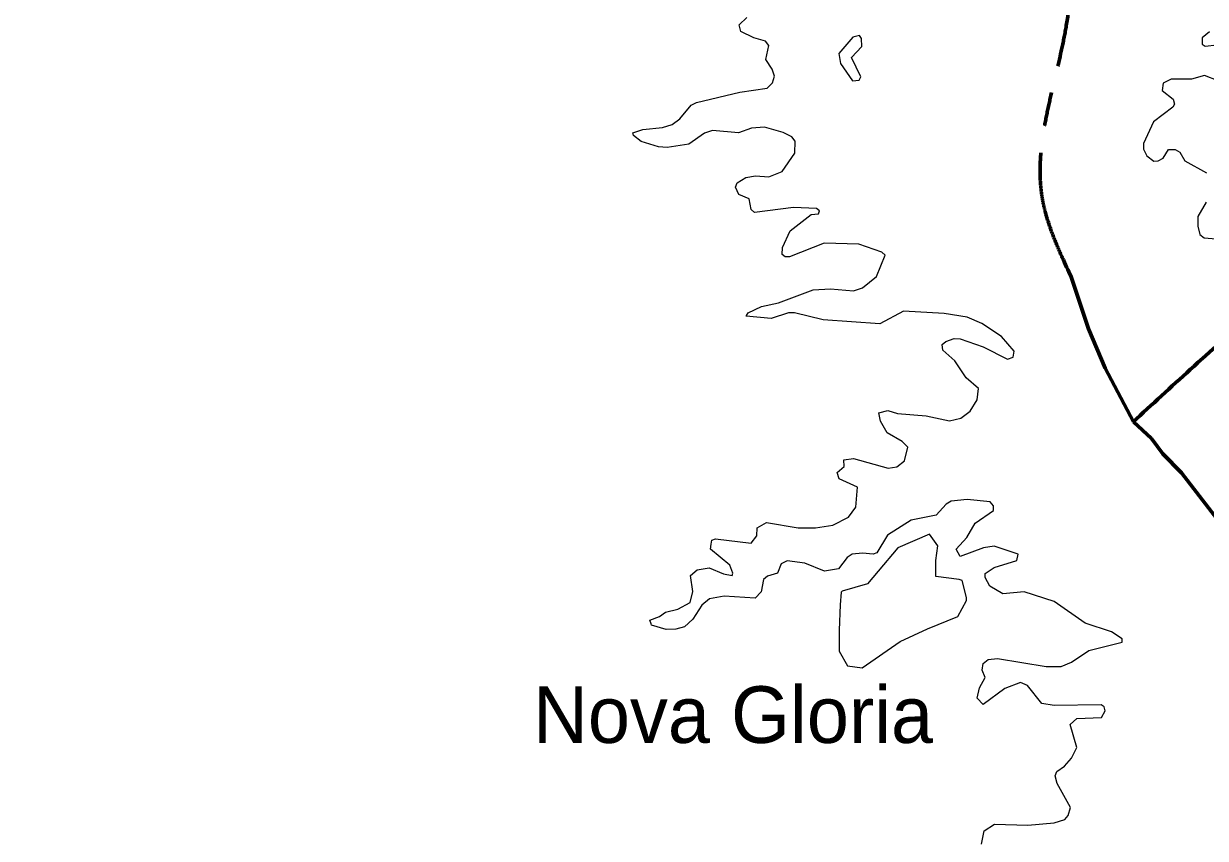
# Model space of a CAD drawing. Extents: x -1643653 to 4543381, y 1624270 to 13878484.
# Drawn here: x 573929 to 584359, y 8965010 to 8972200 of the extents above; entities that cross this region are included whole.
import ezdxf
from ezdxf.enums import TextEntityAlignment as Align

# ---------------------------------------------------------------- set-up
doc = ezdxf.new("R2010")
doc.units = 0
doc.header["$LTSCALE"] = 200
doc.linetypes.add('LONG_DASH_SHORT_DASH', pattern=[9.9, 6, -1.2, 1.5, -1.2])
for name, color, linetype, lineweight in [('21', 7, 'Continuous', 25), ('25', 7, 'Continuous', 13), ('60', 7, 'Continuous', 13), ('7', 7, 'LONG_DASH_SHORT_DASH', 60)]:
    doc.layers.add(name, color=color, linetype=linetype, lineweight=lineweight)
doc.layers.add('41', color=7, linetype='Continuous')

msp = doc.modelspace()

# ---------------------------------------------------------------- linework, layer by layer
at = {"layer": '21'}
msp.add_lwpolyline([(581144.7, 8967182.6), (581135.4, 8967071.1), (581126.2, 8966848.2), (581126.2, 8966662.4), (581200.4, 8966532.3), (581330.4, 8966513.8), (581664.7, 8966746), (581906.1, 8966857.5), (582175.4, 8966968.9), (582249.7, 8967108.2), (582249.7, 8967136.1), (582212.6, 8967284.7), (582184.7, 8967294), (581980.4, 8967321.9), (581980.4, 8967461.2), (581999, 8967591.2), (581924.7, 8967693.4), (581646.1, 8967572.7), (581469.7, 8967368.3), (581376.9, 8967256.9), (581154, 8967191.8)], close=True, dxfattribs=at)
at = {"layer": '25'}
msp.add_line((579471.8, 8966890.6), (579467.6, 8966902.2), dxfattribs=at)
msp.add_line((579471.8, 8966890.6), (579467.6, 8966902.2), dxfattribs=at)
for points in [[(579310.3, 8971213.6), (579305.7, 8971235), (579395.2, 8971264.1), (579567.6, 8971283.5), (579652.3, 8971309), (579720.3, 8971360), (579820.2, 8971478.9), (579869.2, 8971504.5), (580251.6, 8971593.7), (580491.5, 8971629.9), (580538.3, 8971676.8), (580555.1, 8971736.2), (580536, 8971797.3), (580480.8, 8971882.8), (580506.2, 8972005.7), (580476.5, 8972043.8), (580374.6, 8972073.7), (580260.5, 8972130.7), (580245.1, 8972188.4), (580313.2, 8972254.3)], [(579310.3, 8971213.6), (579305.7, 8971235), (579395.2, 8971264.1), (579567.6, 8971283.5), (579652.3, 8971309), (579720.3, 8971360), (579820.2, 8971478.9), (579869.2, 8971504.5), (580251.6, 8971593.7), (580491.5, 8971629.9), (580538.3, 8971676.8), (580555.1, 8971736.2), (580536, 8971797.3), (580480.8, 8971882.8), (580506.2, 8972005.7), (580476.5, 8972043.8), (580374.6, 8972073.7), (580260.5, 8972130.7), (580245.1, 8972188.4), (580313.2, 8972254.3)], [(584395, 8972126.3), (584330, 8972075.8), (584330, 8972018.8), (584357.8, 8972001.5), (584461.6, 8972014.2)], [(584395, 8972126.3), (584330, 8972075.8), (584330, 8972018.8), (584357.8, 8972001.5), (584461.6, 8972014.2)], [(584472.4, 8971696.2), (584351.2, 8971742.2), (584236.4, 8971708.4), (584057.5, 8971710.4), (583985.8, 8971674.1), (583977.4, 8971610.7), (584075.1, 8971531.8), (584087.7, 8971489.6), (584070.5, 8971461.8), (583900.8, 8971334.4), (583811.7, 8971141.1), (583811.7, 8971092.1), (583843.3, 8971033.3), (583905.1, 8970986.2), (583943.3, 8970988.3), (583985.6, 8971013.6), (584034.9, 8971088), (584092, 8971088), (584134.5, 8971066.8), (584177.1, 8970988.3), (584368.2, 8970884.1)], [(584472.4, 8971696.2), (584351.2, 8971742.2), (584236.4, 8971708.4), (584057.5, 8971710.4), (583985.8, 8971674.1), (583977.4, 8971610.7), (584075.1, 8971531.8), (584087.7, 8971489.6), (584070.5, 8971461.8), (583900.8, 8971334.4), (583811.7, 8971141.1), (583811.7, 8971092.1), (583843.3, 8971033.3), (583905.1, 8970986.2), (583943.3, 8970988.3), (583985.6, 8971013.6), (584034.9, 8971088), (584092, 8971088), (584134.5, 8971066.8), (584177.1, 8970988.3), (584368.2, 8970884.1)], [(580309.7, 8969624.7), (580324.1, 8969646.6), (580442.8, 8969703), (580591, 8969734.8), (580897.4, 8969851.8), (581049.8, 8969860.2), (581253.8, 8969843.2), (581332.8, 8969868.9), (581457.9, 8969968.6), (581532.1, 8970155.4), (581503.8, 8970183.4), (581300.7, 8970253.2), (580995.1, 8970263.8), (580689.2, 8970142.9), (580650.8, 8970142.8), (580623.4, 8970161.8), (580627.3, 8970223.2), (580693.7, 8970370.5), (580880.2, 8970516.6), (580943.8, 8970521), (580954.3, 8970548.4), (580926, 8970569.8), (580722.7, 8970576.1), (580378.8, 8970531.6), (580349, 8970559.3), (580332.1, 8970654.5), (580240.8, 8970690.9), (580211.1, 8970756.7), (580226.1, 8970795), (580302.3, 8970841.6), (580387.3, 8970856.5), (580506.2, 8970848.1), (580624.5, 8970894.4), (580735.6, 8971058.1), (580739.9, 8971163.9), (580708, 8971200.6), (580633.5, 8971239), (580468.3, 8971285.6), (580353.1, 8971277.1), (580237.8, 8971236.7), (580009, 8971255.8), (579937.2, 8971232.5), (579937.2, 8971232.5), (579800.8, 8971134.7), (579609.6, 8971107.2), (579533.4, 8971111.5), (579380.7, 8971160.2), (579310.3, 8971213.6)], [(580309.7, 8969624.7), (580324.1, 8969646.6), (580442.8, 8969703), (580591, 8969734.8), (580897.4, 8969851.8), (581049.8, 8969860.2), (581253.8, 8969843.2), (581332.8, 8969868.9), (581457.9, 8969968.6), (581532.1, 8970155.4), (581503.8, 8970183.4), (581300.7, 8970253.2), (580995.1, 8970263.8), (580689.2, 8970142.9), (580650.8, 8970142.8), (580623.4, 8970161.8), (580627.3, 8970223.2), (580693.7, 8970370.5), (580880.2, 8970516.6), (580943.8, 8970521), (580954.3, 8970548.4), (580926, 8970569.8), (580722.7, 8970576.1), (580378.8, 8970531.6), (580349, 8970559.3), (580332.1, 8970654.5), (580240.8, 8970690.9), (580211.1, 8970756.7), (580226.1, 8970795), (580302.3, 8970841.6), (580387.3, 8970856.5), (580506.2, 8970848.1), (580624.5, 8970894.4), (580735.6, 8971058.1), (580739.9, 8971163.9), (580708, 8971200.6), (580633.5, 8971239), (580468.3, 8971285.6), (580353.1, 8971277.1), (580237.8, 8971236.7), (580009, 8971255.8), (579937.2, 8971232.5), (579937.2, 8971232.5), (579800.8, 8971134.7), (579609.6, 8971107.2), (579533.4, 8971111.5), (579380.7, 8971160.2), (579310.3, 8971213.6)], [(584364.7, 8970623), (584293.8, 8970497.2), (584291.7, 8970412.5), (584311, 8970338.1), (584347.1, 8970310.6), (584528.8, 8970293.7)], [(584364.7, 8970623), (584293.8, 8970497.2), (584291.7, 8970412.5), (584311, 8970338.1), (584347.1, 8970310.6), (584528.8, 8970293.7)], [(579997.9, 8967607), (580002.2, 8967641.4), (580036, 8967653.3), (580349.3, 8967615), (580399.9, 8967680.5), (580404.5, 8967748.8), (580485.3, 8967797.5), (580765.4, 8967750.9), (580918.4, 8967748.8), (581071.3, 8967774.2), (581209.4, 8967844.3), (581273.1, 8967931.4), (581290, 8968109.6), (581126.5, 8968182.3), (581109.5, 8968238.9), (581170.9, 8968290.2), (581167, 8968349.8), (581254, 8968362.6), (581560.2, 8968277.7), (581636.5, 8968288.5), (581702.2, 8968341.5), (581733.9, 8968462.6), (581683.1, 8968511.3), (581551.5, 8968590), (581492, 8968691.9), (581477.3, 8968766.3), (581557.6, 8968785.3), (581642.9, 8968759.5), (581895.5, 8968738.6), (582099.5, 8968694), (582201.4, 8968717.4), (582282.1, 8968781.1), (582343.8, 8968879.1), (582356.4, 8968980.7), (582248.2, 8969074.3), (582148.5, 8969222.7), (582042.2, 8969318.6), (582035.8, 8969367.1), (582067.6, 8969395), (582142, 8969420.5), (582195.2, 8969417.7), (582396.8, 8969348.3), (582613.7, 8969237.8), (582662.3, 8969257), (582672.9, 8969307.9), (582558.3, 8969437.5), (582387.3, 8969552.8), (582256.4, 8969609.6), (582053, 8969641.4), (581695.9, 8969662.6), (581486.8, 8969550.1), (580986.3, 8969586.2), (580731.4, 8969647.8), (580680.5, 8969647.7), (580527.5, 8969596.8), (580305.1, 8969617.7), (580309.7, 8969624.7)], [(579997.9, 8967607), (580002.2, 8967641.4), (580036, 8967653.3), (580349.3, 8967615), (580399.9, 8967680.5), (580404.5, 8967748.8), (580485.3, 8967797.5), (580765.4, 8967750.9), (580918.4, 8967748.8), (581071.3, 8967774.2), (581209.4, 8967844.3), (581273.1, 8967931.4), (581290, 8968109.6), (581126.5, 8968182.3), (581109.5, 8968238.9), (581170.9, 8968290.2), (581167, 8968349.8), (581254, 8968362.6), (581560.2, 8968277.7), (581636.5, 8968288.5), (581702.2, 8968341.5), (581733.9, 8968462.6), (581683.1, 8968511.3), (581551.5, 8968590), (581492, 8968691.9), (581477.3, 8968766.3), (581557.6, 8968785.3), (581642.9, 8968759.5), (581895.5, 8968738.6), (582099.5, 8968694), (582201.4, 8968717.4), (582282.1, 8968781.1), (582343.8, 8968879.1), (582356.4, 8968980.7), (582248.2, 8969074.3), (582148.5, 8969222.7), (582042.2, 8969318.6), (582035.8, 8969367.1), (582067.6, 8969395), (582142, 8969420.5), (582195.2, 8969417.7), (582396.8, 8969348.3), (582613.7, 8969237.8), (582662.3, 8969257), (582672.9, 8969307.9), (582558.3, 8969437.5), (582387.3, 8969552.8), (582256.4, 8969609.6), (582053, 8969641.4), (581695.9, 8969662.6), (581486.8, 8969550.1), (580986.3, 8969586.2), (580731.4, 8969647.8), (580680.5, 8969647.7), (580527.5, 8969596.8), (580305.1, 8969617.7), (580309.7, 8969624.7)], [(582384.1, 8964957.7), (582407.6, 8965076.4), (582498.3, 8965133.6), (582792, 8965127.4), (583025.6, 8965146.5), (583119.2, 8965176.5), (583148.8, 8965212.4), (583170, 8965280.6), (583051.2, 8965492.5), (583034.2, 8965562.9), (583049.1, 8965601.1), (583114.8, 8965645.7), (583178, 8965717.2), (583225.2, 8965811.2), (583165.9, 8966013.2), (583223.5, 8966068.5), (583441.9, 8966077), (583475.9, 8966134.3), (583465.2, 8966170.4), (583439.6, 8966189.4), (583025.6, 8966183.2), (582915.7, 8966200), (582789.8, 8966359.4), (582728.2, 8966384.9), (582588.1, 8966331.8), (582396.7, 8966191.8), (582346, 8966247.1), (582364.9, 8966338), (582415.8, 8966429.6), (582390.2, 8966492.9), (582396.9, 8966552.7), (582441.5, 8966588.8), (582524.1, 8966597.4), (582953.4, 8966525.2), (583085.1, 8966527.3), (583178.8, 8966563.5), (583331.5, 8966667.5), (583624.5, 8966739.8), (583624.6, 8966771.3), (583531.2, 8966831), (583297.3, 8966909.8), (583025.6, 8967098.7), (582760.3, 8967185.7), (582571.1, 8967166.8), (582456.7, 8967236.5), (582416, 8967311.4), (582416.1, 8967347.1), (582494.8, 8967400.4), (582694, 8967461.9), (582706.9, 8967517.1), (582494.3, 8967589.4), (582401.1, 8967574.5), (582195.1, 8967498.2), (582159.1, 8967561.8), (582254.4, 8967663.6), (582326.8, 8967791.2), (582488.1, 8967904.1), (582488.1, 8967944.1), (582458.3, 8967980.2), (582256.4, 8967999.4), (582116.5, 8967984.5), (582071.9, 8967959), (581982.3, 8967861.3), (581763.8, 8967818.8), (581553.6, 8967684.9), (581459.8, 8967529.9), (581427.3, 8967517.2), (581332, 8967527.8), (581241.1, 8967517), (581198.8, 8967489.5), (581119.9, 8967389.7), (580998.9, 8967368.6), (580825.2, 8967438.5), (580667.5, 8967459.7), (580614.4, 8967431.8), (580582.4, 8967349.3), (580493.6, 8967323.8), (580457.7, 8967294.3), (580438.2, 8967185.8), (580385.3, 8967130.7), (580111.4, 8967147.6), (579983.5, 8967124), (579915.9, 8967069.1), (579835, 8966943.6), (579762.8, 8966875.7), (579686.3, 8966854.5), (579601.1, 8966852.3), (579471.8, 8966890.6)], [(582384.1, 8964957.7), (582407.6, 8965076.4), (582498.3, 8965133.6), (582792, 8965127.4), (583025.6, 8965146.5), (583119.2, 8965176.5), (583148.8, 8965212.4), (583170, 8965280.6), (583051.2, 8965492.5), (583034.2, 8965562.9), (583049.1, 8965601.1), (583114.8, 8965645.7), (583178, 8965717.2), (583225.2, 8965811.2), (583165.9, 8966013.2), (583223.5, 8966068.5), (583441.9, 8966077), (583475.9, 8966134.3), (583465.2, 8966170.4), (583439.6, 8966189.4), (583025.6, 8966183.2), (582915.7, 8966200), (582789.8, 8966359.4), (582728.2, 8966384.9), (582588.1, 8966331.8), (582396.7, 8966191.8), (582346, 8966247.1), (582364.9, 8966338), (582415.8, 8966429.6), (582390.2, 8966492.9), (582396.9, 8966552.7), (582441.5, 8966588.8), (582524.1, 8966597.4), (582953.4, 8966525.2), (583085.1, 8966527.3), (583178.8, 8966563.5), (583331.5, 8966667.5), (583624.5, 8966739.8), (583624.6, 8966771.3), (583531.2, 8966831), (583297.3, 8966909.8), (583025.6, 8967098.7), (582760.3, 8967185.7), (582571.1, 8967166.8), (582456.7, 8967236.5), (582416, 8967311.4), (582416.1, 8967347.1), (582494.8, 8967400.4), (582694, 8967461.9), (582706.9, 8967517.1), (582494.3, 8967589.4), (582401.1, 8967574.5), (582195.1, 8967498.2), (582159.1, 8967561.8), (582254.4, 8967663.6), (582326.8, 8967791.2), (582488.1, 8967904.1), (582488.1, 8967944.1), (582458.3, 8967980.2), (582256.4, 8967999.4), (582116.5, 8967984.5), (582071.9, 8967959), (581982.3, 8967861.3), (581763.8, 8967818.8), (581553.6, 8967684.9), (581459.8, 8967529.9), (581427.3, 8967517.2), (581332, 8967527.8), (581241.1, 8967517), (581198.8, 8967489.5), (581119.9, 8967389.7), (580998.9, 8967368.6), (580825.2, 8967438.5), (580667.5, 8967459.7), (580614.4, 8967431.8), (580582.4, 8967349.3), (580493.6, 8967323.8), (580457.7, 8967294.3), (580438.2, 8967185.8), (580385.3, 8967130.7), (580111.4, 8967147.6), (579983.5, 8967124), (579915.9, 8967069.1), (579835, 8966943.6), (579762.8, 8966875.7), (579686.3, 8966854.5), (579601.1, 8966852.3), (579471.8, 8966890.6)], [(579467.6, 8966902.2), (579455.3, 8966936.2), (579541.6, 8966967.5), (579595, 8967007.3), (579704, 8967033.2), (579811.7, 8967092.6), (579835, 8967188.5), (579813.9, 8967330.2), (579873.1, 8967378.9), (579979.2, 8967396.1), (580105, 8967343), (580105, 8967343), (580181.1, 8967330.4), (580187.4, 8967349.7), (580161, 8967421.7), (579992.3, 8967561.8), (579997.9, 8967607)], [(579467.6, 8966902.2), (579455.3, 8966936.2), (579541.6, 8966967.5), (579595, 8967007.3), (579704, 8967033.2), (579811.7, 8967092.6), (579835, 8967188.5), (579813.9, 8967330.2), (579873.1, 8967378.9), (579979.2, 8967396.1), (580105, 8967343), (580105, 8967343), (580181.1, 8967330.4), (580187.4, 8967349.7), (580161, 8967421.7), (579992.3, 8967561.8), (579997.9, 8967607)]]:
    msp.add_lwpolyline(points, dxfattribs=at)
msp.add_lwpolyline([(581237.1, 8971901.1), (581328.3, 8971997.6), (581324, 8972069.6), (581307.2, 8972094.7), (581247.3, 8972081.7), (581124.6, 8971937.6), (581139.6, 8971848.2), (581245.5, 8971693.7), (581304.9, 8971699.9), (581317.6, 8971731.5)], close=True, dxfattribs=at)
msp.add_lwpolyline([(581237.1, 8971901.1), (581328.3, 8971997.6), (581324, 8972069.6), (581307.2, 8972094.7), (581247.3, 8972081.7), (581124.6, 8971937.6), (581139.6, 8971848.2), (581245.5, 8971693.7), (581304.9, 8971699.9), (581317.6, 8971731.5)], close=True, dxfattribs=at)
at = {"layer": '60', "lineweight": 25}
msp.add_spline([(814781, 9009175.5), (814787.2, 9009173.4), (814796.9, 9009173.4), (814799.4, 9009172.4), (814805.1, 9009174.5), (814805.6, 9009176.5), (814811.7, 9009179.5), (814811.7, 9009179.5), (814801.5, 9009181), (814790.7, 9009181.5), (814784.1, 9009183.1), (814777.4, 9009185.1), (814778.4, 9009175.5)], degree=3, dxfattribs=at)
at = {"layer": '7'}
msp.add_lwpolyline([(583174.4, 8969966), (583327.9, 8969505.4), (583474.7, 8969160.4), (583725.5, 8968684.8), (583883.2, 8968539.9), (583982.9, 8968403.5), (584146.9, 8968235.1), (584624.8, 8967616.6), (584992.2, 8967072.1), (585186.8, 8966825.7), (585377.2, 8966655.9), (585748.8, 8966438.6), (585960.5, 8966257.3), (586351.6, 8965976.8), (586551, 8965796.4), (587006.6, 8965310.9), (587303.1, 8964815.2), (587426.7, 8964495.3)], dxfattribs=at)
for points in [[(581705.4, 8974333.7), (582461.9, 8973819.1), (583080, 8973133.9), (583131.7, 8972182.4), (582921.5, 8970648.2), (583174.4, 8969966)], [(583719.8, 8968683.1), (584226, 8969147.1), (585263.8, 8970159.6), (585803.8, 8970817.7), (586453.4, 8971391.4), (587077.8, 8971939.8), (587744.3, 8972277.3), (588469.9, 8972403.9), (588728.8, 8972391.8)]]:
    msp.add_spline(points, degree=3, dxfattribs=at)

# ---------------------------------------------------------------- texts
at = {"layer": '41'}
msp.add_text('Nova Gloria', height=500, dxfattribs=at).set_placement((580191.1, 8965851.8), align=Align.CENTER)

doc.saveas('drawing.dxf')
